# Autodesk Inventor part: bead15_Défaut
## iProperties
Shininess: 64.0
Length Units: 11269
Angle Units: 11279
Time Units: 11290
Mass Units: 11283
Length Display Precision: 3
Angle Display Precision: 2
Compacted: True
Part Number: bead15_Défaut
Document SubType Name: Modeling
Created: 2006-01
Material: Par défaut
Designer: Fricot
Density: 0.0
Volumn: 0.0
Area: 0.0
PropertySet Name: Model Information
Control State: 0
Master: False
Checked Out: False
Author: Fricot
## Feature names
1. Base1
